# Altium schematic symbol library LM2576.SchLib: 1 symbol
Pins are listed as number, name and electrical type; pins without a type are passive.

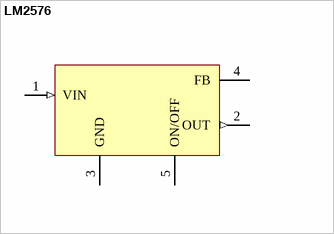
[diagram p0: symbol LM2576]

## LM2576
designator U?
pins: 1 VIN (in), 2 OUT (out), 3 GND (power), 4 FB, 5 ON/OFF (power)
